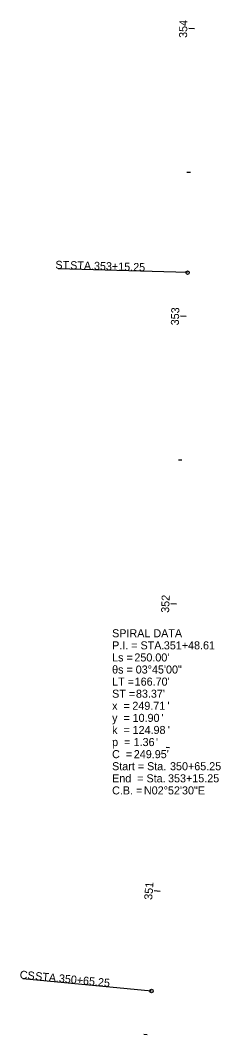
# Model space of a CAD drawing. Extents: x 1380777 to 1381940, y 503546 to 507267.
# Drawn here: x 1381703.7 to 1381773.4, y 505015.1 to 505367.6 of the extents above; entities that cross this region are included whole.
import ezdxf

# ---------------------------------------------------------------- set-up
doc = ezdxf.new("R2010")
doc.units = 0
for name, color, linetype in [('GE_X_Alignment_100_Curve_Data', 7, 'Continuous'), ('GE_X_Alignment_100_Stations', 7, 'Continuous'), ('GE_X_Alignment_500_Stations', 7, 'Continuous')]:
    doc.layers.add(name, color=color, linetype=linetype)

msp = doc.modelspace()

# ---------------------------------------------------------------- linework, layer by layer
at = {"layer": 'GE_X_Alignment_100_Stations'}
for p, q in [((1381761.87, 505279.88), (1381716.89, 505281.16)), ((1381749.33, 505030.25), (1381704.53, 505034.47))]:
    msp.add_line(p, q, dxfattribs=at)
for centre in [(1381761.87, 505279.88), (1381749.33, 505030.25)]:
    msp.add_circle(centre, 0.6, dxfattribs=at)
at = {"layer": 'GE_X_Alignment_500_Stations'}
for p, q in [((1381764.27, 505364.6), (1381762.27, 505364.66)), ((1381762.85, 505314.62), (1381761.65, 505314.66)), ((1381761.43, 505264.65), (1381759.44, 505264.71)), ((1381759.92, 505214.67), (1381758.72, 505214.71)), ((1381758.07, 505164.71), (1381756.07, 505164.79)), ((1381755.61, 505114.77), (1381754.41, 505114.84)), ((1381752.29, 505064.88), (1381750.29, 505065.04)), ((1381747.84, 505015.08), (1381746.65, 505015.2))]:
    msp.add_line(p, q, dxfattribs=at)

# ---------------------------------------------------------------- texts
at = {"layer": 'GE_X_Alignment_100_Curve_Data'}
for s, p in [('SPIRAL DATA', (1381735.62, 505153.17)), ('P.I. = STA. ', (1381735.62, 505148.97)), ('351+48.61', (1381753.61, 505148.97)), ('Ls = ', (1381735.62, 505144.77)), ("250.00'", (1381743.37, 505144.77)), ('θs = ', (1381735.62, 505140.57)), ('03°45\'00"', (1381743.83, 505140.57)), ('LT = ', (1381735.62, 505136.37)), ("166.70'", (1381743.47, 505136.37)), ('ST = ', (1381735.62, 505132.17)), ("83.37'", (1381743.92, 505132.17)), ('x  = ', (1381735.62, 505127.97)), ('249.71', (1381742.65, 505127.97)), ("'", (1381754.9, 505127.97)), ('y  = ', (1381735.62, 505123.77)), ('10.90', (1381742.75, 505123.77)), ("'", (1381752.77, 505123.77)), ('k  = ', (1381735.62, 505119.57)), ('124.98', (1381742.75, 505119.57)), ("'", (1381755, 505119.57)), ('p  = ', (1381735.62, 505115.37)), ('1.36', (1381743.1, 505115.37)), ("'", (1381750.88, 505115.37)), ('C  = ', (1381735.62, 505111.17)), ("249.95'", (1381743.17, 505111.17)), ('Start = Sta. ', (1381735.62, 505106.97)), ('350+65.25', (1381755.77, 505106.97)), ('End  = Sta. ', (1381735.62, 505102.77)), ('353+15.25', (1381755.08, 505102.77)), ('C.B. = ', (1381735.62, 505098.57)), ('N02°52\'30"E', (1381746.69, 505098.57))]:
    msp.add_text(s, height=2.8, dxfattribs=at).set_placement(p)
at = {"layer": 'GE_X_Alignment_100_Stations'}
for s, rotation, p in [('ST', 358.375, (1381715.86, 505281.23)), (' STA. ', 358.375, (1381719.96, 505281.11)), ('353+15.25', 358.375, (1381729.28, 505280.85)), ('CS', 354.625, (1381703.38, 505034.61)), (' STA. ', 354.625, (1381707.72, 505034.21)), ('350+65.25', 354.625, (1381717, 505033.33))]:
    msp.add_text(s, height=2.8, rotation=rotation, dxfattribs=at).set_placement(p)
at = {"layer": 'GE_X_Alignment_500_Stations'}
for s, rotation, p in [('354', 88.375, (1381761.68, 505361.4)), ('353', 88.3611, (1381758.84, 505261.53)), ('352', 87.5781, (1381755.43, 505161.61)), ('351', 85.5952, (1381749.55, 505061.86))]:
    msp.add_text(s, height=2.8, rotation=rotation, dxfattribs=at).set_placement(p)

doc.saveas('drawing.dxf')
